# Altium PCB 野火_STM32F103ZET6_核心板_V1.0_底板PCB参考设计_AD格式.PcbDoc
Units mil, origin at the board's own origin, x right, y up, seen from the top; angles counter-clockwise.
Board outline 3896.24 x 5247.31 mil, 2 copper layers (TOP, BOTTOM), stack 10.4 mil thick; 6 components, 115 nets, 124 pads, 0 vias.
Unrouted connection lines stored in the file: 8.
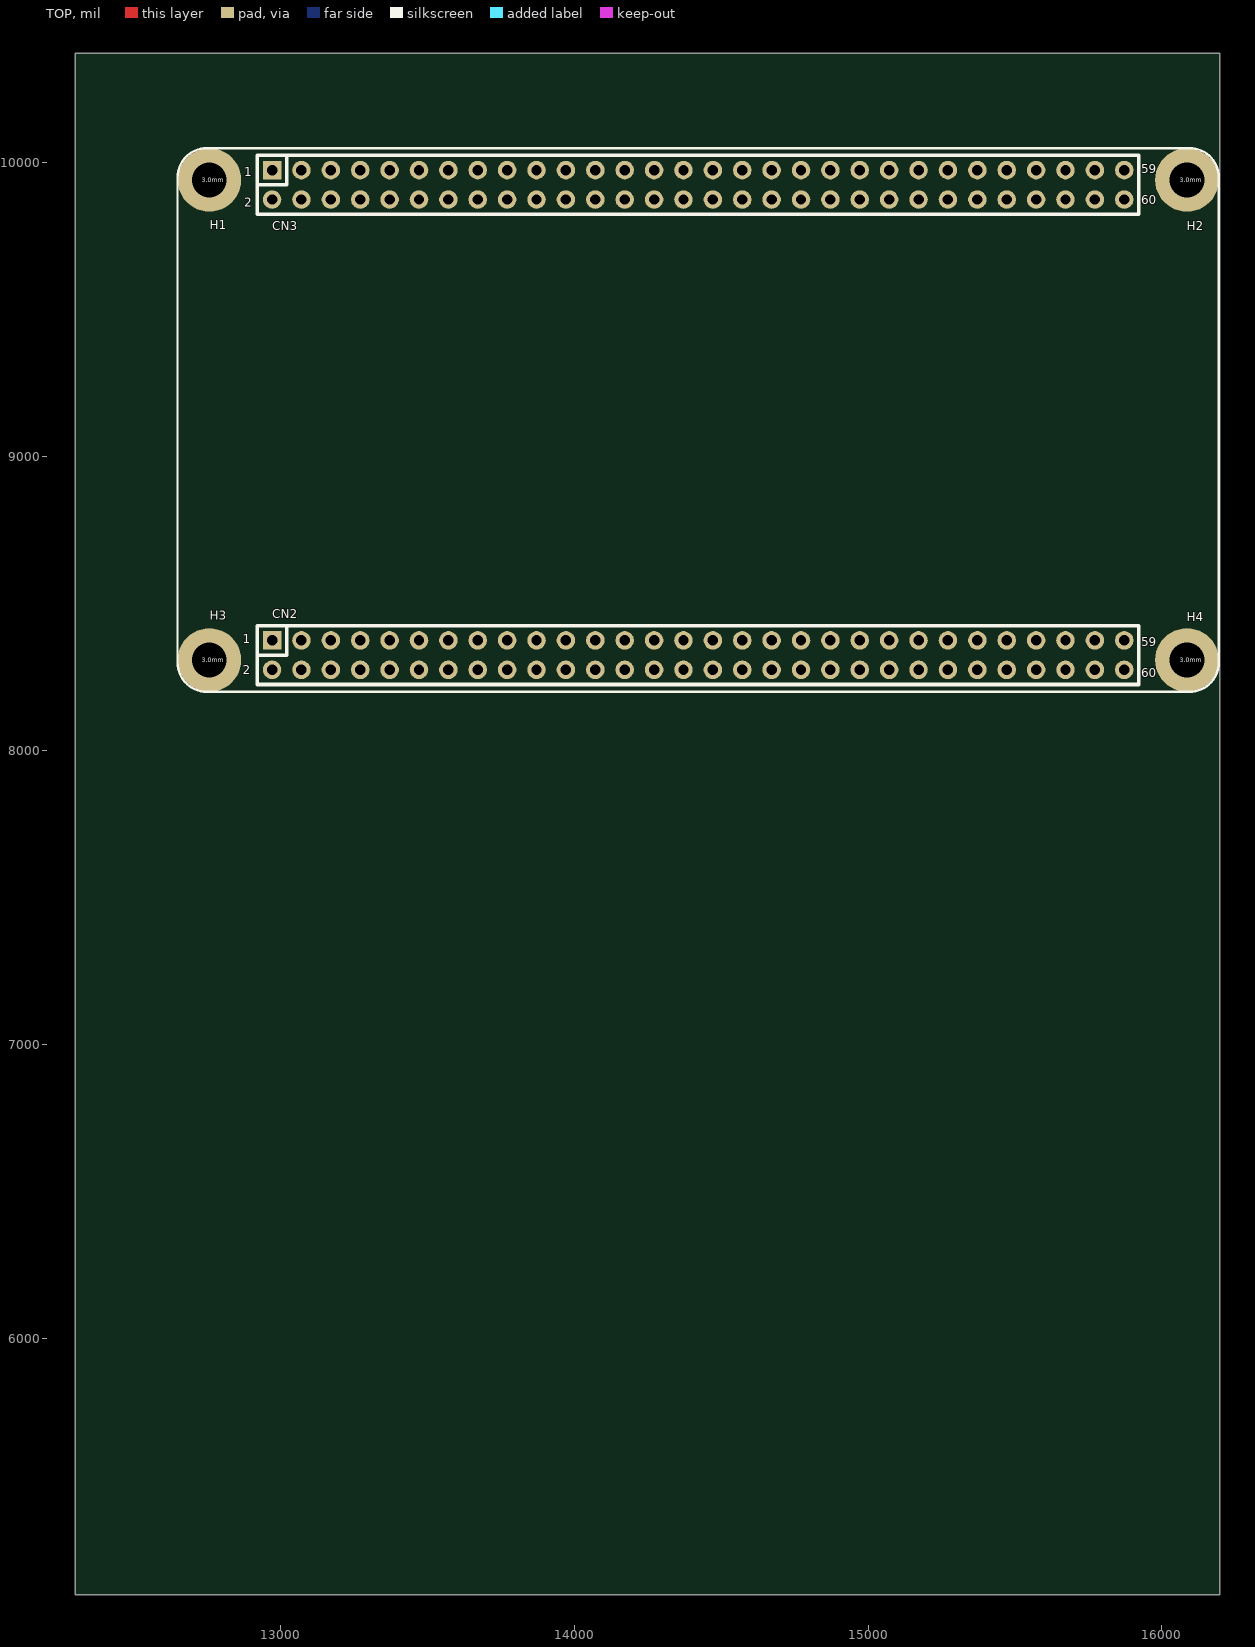
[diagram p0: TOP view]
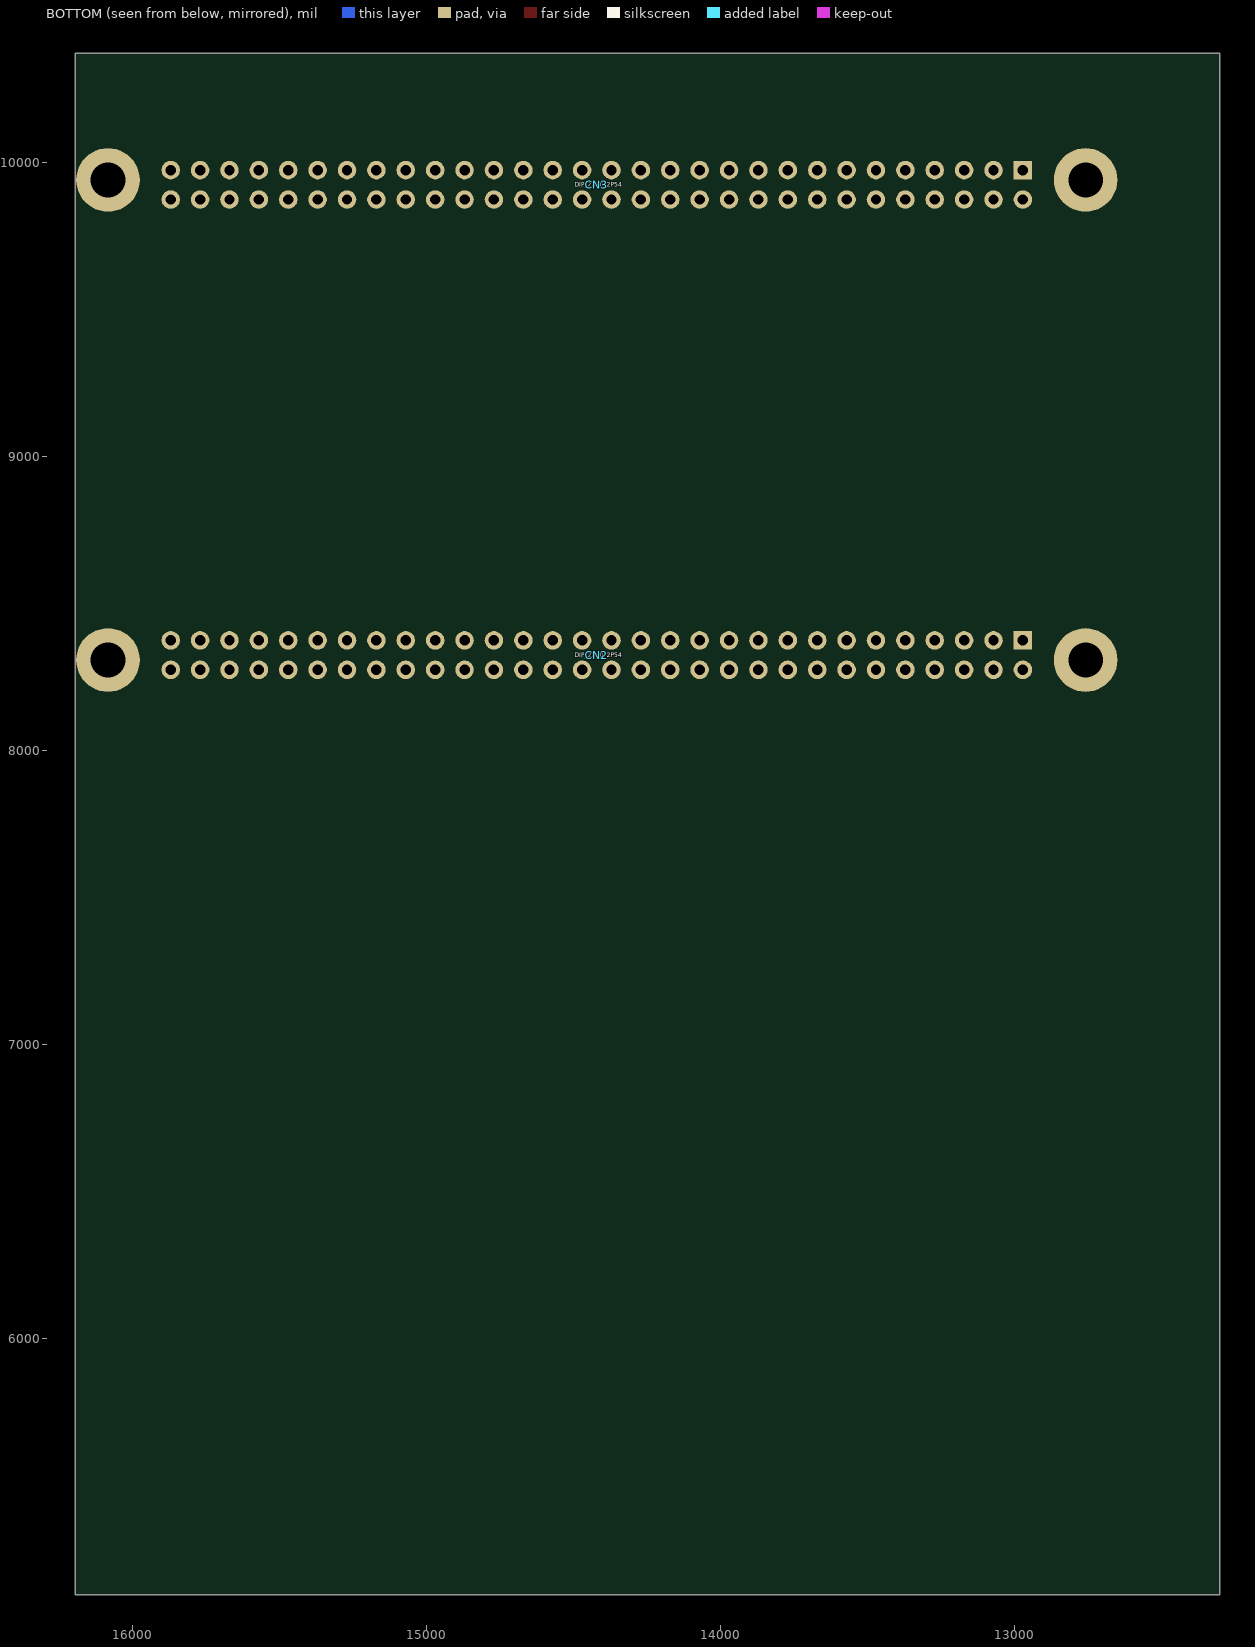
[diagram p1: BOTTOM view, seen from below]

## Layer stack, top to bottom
TOP: signal copper 1.2
Dielectric: core 8, FR-4, Dk 4.5
BOTTOM: signal copper 1.2

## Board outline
12301.07,5126.62 16197.31,5126.62 16197.31,10373.93 12301.07,10373.93

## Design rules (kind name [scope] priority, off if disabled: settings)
Clearance [All] p1: gap=10
PlaneConnect [All] p1: planeconnectstyle=Direct reliefexpansion=20 reliefentries=4 reliefconductorwidth=10 reliefairgap=10
PolygonConnect [All] p1: connectstyle=Direct reliefconductorwidth=10 reliefentries=4 polygonreliefangle="90 Angle" airgapwidth=10
RoutingVias [All] p1: holewidth=28 width=50 viastyle="Through Hole" minholewidth=28 minwidth=50 maxholewidth=28 maxwidth=50
SolderMaskExpansion [All] p1: expansion=4
Width [All] p1: maxlimit=10 minlimit=10 preferedwidth=10 impedancedriven=TRUE minimp=0.000000 maximp=0.000000 favimp=100000000000000005400000000000000.000000
27 further rules are at their usual default settings.

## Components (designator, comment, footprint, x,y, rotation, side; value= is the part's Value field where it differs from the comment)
CN2 "DIP_2X40_0_DIP-2X302P54_DIP_2X3" DIP-2X302P54 14431.15,8325 r180 bottom
CN3 "DIP_2X40_0_DIP-2X302P54_DIP_2X3" DIP-2X302P54 14431.15,9925.39 r180 bottom
H1 "SPACER_0_T3-5P5_IC_3.0MM" T3-5P5 12758.26,9942.13 r0 top
H2 "SPACER_0_T3-5P5_IC_3.0MM" T3-5P5 16085.04,9942.13 r0 top
H3 "SPACER_0_T3-5P5_IC_3.0MM" T3-5P5 12758.26,8308.26 r0 top
H4 "SPACER_0_T3-5P5_IC_3.0MM" T3-5P5 16085.04,8308.26 r0 top

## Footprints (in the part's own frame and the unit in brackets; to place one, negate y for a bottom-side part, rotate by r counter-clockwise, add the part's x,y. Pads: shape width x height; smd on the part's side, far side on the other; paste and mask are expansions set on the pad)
DIP-2X302P54 [mil] "DIP-2X302P54"
  rect 62.99x62.99 / inner round 60 / far side rect 62.99x62.99 hole 35.43: 1(1459.5,50)
  round 62.99 / inner round 60 / far side round 62.99 hole 35.43: 2(1459.5,-50) 3(1359.5,50) 4(1359.5,-50) 5(1259.5,50) 6(1259.5,-50) 7(1159.5,50) 8(1159.5,-50) 9(1059.5,50) 10(1059.5,-50) 11(959.5,50) 12(959.5,-50) 13(859.5,50) 14(859.5,-50) 15(759.5,50) 16(759.5,-50) 17(659.5,50) 18(659.5,-50) 19(559.5,50) 20(559.5,-50) 21(459.5,50) 22(459.5,-50) 23(359.5,50) 24(359.5,-50) 25(259.5,50) 26(259.5,-50) 27(159.5,50) 28(159.5,-50) 29(59.5,50) 30(59.5,-50) 31(-40.5,50) 32(-40.5,-50) 33(-140.5,50) 34(-140.5,-50) 35(-240.5,50) 36(-240.5,-50) 37(-340.5,50) 38(-340.5,-50) 39(-440.5,50) 40(-440.5,-50) 41(-540.5,50) 42(-540.5,-50) 43(-640.5,50) 44(-640.5,-50) 45(-740.5,50) 46(-740.5,-50) 47(-840.5,50) 48(-840.5,-50) 49(-940.5,50) 50(-940.5,-50) 51(-1040.5,50) 52(-1040.5,-50) 53(-1140.5,50) 54(-1140.5,-50) 55(-1240.5,50) 56(-1240.5,-50) 57(-1340.5,50) 58(-1340.5,-50) 59(-1440.5,50) 60(-1440.5,-50)
T3-5P5 [mm] "T3-5P5"
  round 5.5 / inner round 1.524 / far side round 5.5 hole 3: 1(0,0)

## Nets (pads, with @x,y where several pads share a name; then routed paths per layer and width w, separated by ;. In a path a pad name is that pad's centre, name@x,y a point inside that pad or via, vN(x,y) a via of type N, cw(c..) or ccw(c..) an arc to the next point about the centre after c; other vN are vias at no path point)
3V3: CN2.59 CN2.60
BOOT0: CN2.9
GND: CN2.7 CN2.8 CN2.57 CN2.58 CN3.46 H1.1 H2.1 H3.1 H4.1
NRST: CN3.6
PA0/WKUP: CN2.55
PA1: CN3.59
PA2: CN2.12
PA3: CN2.14
PA4: CN2.1
PA5: CN2.2
PA6: CN2.3
PA7: CN2.4
PA8: CN3.19
PA9: CN2.11
PA10: CN2.13
PA11: CN3.37
PA12: CN3.38
PA13: CN3.3
PA14: CN3.2
PA15: CN3.1
PB0: CN2.52
PB1: CN2.53
PB2: CN2.10
PB3: CN3.4
PB4: CN3.5
PB5: CN2.51
PB6: CN2.5
PB7: CN2.6
PB8: CN3.22
PB9: CN3.24
PB10: CN3.26
PB11: CN3.28
PB12: CN3.13
PB13: CN3.8
PB14: CN3.9
PB15: CN3.10
PC0: CN3.29
PC1: CN3.32
PC2: CN3.31
PC3: CN3.15
PC4: CN3.23
PC5: CN3.17
PC6: CN3.27
PC7: CN3.30
PC8: CN3.53
PC9: CN3.55
PC10: CN3.57
PC11: CN3.54
PC12: CN3.58
PC13/TAMPER: CN2.56
PD0: CN2.37
PD1: CN2.38
PD2: CN3.56
PD3: CN3.20
PD4: CN3.41
PD5: CN3.42
PD6: CN3.18
PD7: CN3.52
PD8: CN2.48
PD9: CN2.49
PD10: CN2.50
PD11: CN2.31
PD12: CN2.32
PD13: CN2.33
PD14: CN2.35
PD15: CN2.36
PE0: CN3.43
PE1: CN3.44
PE2: CN3.39
PE3: CN3.14
PE4: CN3.25
PE5: CN3.21
PE6: CN3.16
PE7: CN2.39
PE8: CN2.40
PE9: CN2.41
PE10: CN2.42
PE11: CN2.43
PE12: CN2.44
PE13: CN2.45
PE14: CN2.46
PE15: CN2.47
PF0: CN2.15
PF1: CN2.16
PF2: CN2.17
PF3: CN2.18
PF4: CN2.19
PF5: CN2.20
PF6: CN3.34
PF7: CN3.36
PF8: CN2.54
PF9: CN3.47
PF10: CN3.49
PF11: CN3.50
PF12: CN2.21
PF13: CN2.22
PF14: CN2.23
PF15: CN2.24
PG0: CN2.25
PG1: CN2.26
PG2: CN2.27
PG3: CN2.28
PG4: CN2.29
PG5: CN2.30
PG6: CN3.35
PG7: CN3.33
PG8: CN3.11
PG9: CN3.7
PG10: CN3.40
PG11: CN3.48
PG12: CN2.34
PG13: CN3.45
PG14: CN3.51
PG15: CN3.12
VBAT: CN3.60

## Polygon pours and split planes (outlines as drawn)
no net on Top Solder (solid): 16193.31,8299.99 16193.31,8416.53 16085.04,8416.53 16075.6,8416.12 16066.24,8414.89 16057.02,8412.84 16048.01,8410 16039.28,8406.39 16030.91,8402.02 16022.94,8396.95 16015.45,8391.2 16008.48,8384.82 16002.1,8377.85 15996.35,8370.36 15991.28,8362.4 15986.91,8354.02 15983.3,8345.29 15980.46,8336.28 15978.41,8327.06 15977.18,8317.7 15976.77,8308.26 15976.77,8199.99 16093.31,8199.99 16102.03,8200.37 16110.67,8201.51 16119.19,8203.4 16127.51,8206.02 16135.57,8209.36 16143.31,8213.39 16150.67,8218.07 16157.59,8223.39 16164.02,8229.28 16169.91,8235.71 16175.23,8242.63 16179.91,8249.99 16183.94,8257.73 16187.28,8265.79 16189.9,8274.11 16191.79,8282.63 16192.93,8291.27 16193.31,8299.99
no net on Top Solder (solid): 16193.31,9833.86 16193.31,9950.4 16192.93,9959.12 16191.79,9967.76 16189.9,9976.28 16187.28,9984.6 16183.94,9992.66 16179.91,10000.4 16175.23,10007.76 16169.91,10014.68 16164.02,10021.11 16157.59,10027 16150.67,10032.32 16143.31,10037 16135.57,10041.03 16127.51,10044.37 16119.19,10046.99 16110.67,10048.88 16102.03,10050.02 16093.31,10050.4 15976.77,10050.4 15976.77,9942.13 15977.18,9932.69 15978.41,9923.33 15980.46,9914.11 15983.3,9905.1 15986.91,9896.37 15991.28,9888 15996.35,9880.03 16002.1,9872.54 16008.48,9865.57 16015.45,9859.19 16022.94,9853.44 16030.91,9848.37 16039.28,9844 16048.01,9840.39 16057.02,9837.55 16066.24,9835.5 16075.6,9834.27 16085.04,9833.86 16193.31,9833.86
no net on Top Solder (solid): 12866.53,8199.99 12866.53,8308.26 12866.12,8317.7 12864.89,8327.06 12862.84,8336.28 12860,8345.29 12856.39,8354.02 12852.02,8362.4 12846.95,8370.36 12841.2,8377.85 12834.82,8384.82 12827.85,8391.2 12820.36,8396.95 12812.4,8402.02 12804.02,8406.39 12795.29,8410 12786.28,8412.84 12777.06,8414.89 12767.7,8416.12 12758.26,8416.53 12649.99,8416.53 12649.99,8299.99 12650.37,8291.27 12651.51,8282.63 12653.4,8274.11 12656.02,8265.79 12659.36,8257.73 12663.39,8249.99 12668.07,8242.63 12673.39,8235.71 12679.28,8229.28 12685.71,8223.39 12692.63,8218.07 12699.99,8213.39 12707.73,8209.36 12715.79,8206.02 12724.11,8203.4 12732.63,8201.51 12741.27,8200.37 12749.99,8199.99 12866.53,8199.99
no net on Top Solder (solid): 12866.53,9942.13 12866.53,10050.4 12749.99,10050.4 12741.27,10050.02 12732.63,10048.88 12724.11,10046.99 12715.79,10044.37 12707.73,10041.03 12699.99,10037 12692.63,10032.32 12685.71,10027 12679.28,10021.11 12673.39,10014.68 12668.07,10007.76 12663.39,10000.4 12659.36,9992.66 12656.02,9984.6 12653.4,9976.28 12651.51,9967.76 12650.37,9959.12 12649.99,9950.4 12649.99,9833.86 12758.26,9833.86 12767.7,9834.27 12777.06,9835.5 12786.28,9837.55 12795.29,9840.39 12804.02,9844 12812.4,9848.37 12820.36,9853.44 12827.85,9859.19 12834.82,9865.57 12841.2,9872.54 12846.95,9880.03 12852.02,9888 12856.39,9896.37 12860,9905.1 12862.84,9914.11 12864.89,9923.33 12866.12,9932.69 12866.53,9942.13
no net on Bottom Solder (solid): 16193.31,8299.99 16193.31,8416.53 16085.04,8416.53 16075.6,8416.12 16066.24,8414.89 16057.02,8412.84 16048.01,8410 16039.28,8406.39 16030.91,8402.02 16022.94,8396.95 16015.45,8391.2 16008.48,8384.82 16002.1,8377.85 15996.35,8370.36 15991.28,8362.4 15986.91,8354.02 15983.3,8345.29 15980.46,8336.28 15978.41,8327.06 15977.18,8317.7 15976.77,8308.26 15976.77,8199.99 16093.31,8199.99 16102.03,8200.37 16110.67,8201.51 16119.19,8203.4 16127.51,8206.02 16135.57,8209.36 16143.31,8213.39 16150.67,8218.07 16157.59,8223.39 16164.02,8229.28 16169.91,8235.71 16175.23,8242.63 16179.91,8249.99 16183.94,8257.73 16187.28,8265.79 16189.9,8274.11 16191.79,8282.63 16192.93,8291.27 16193.31,8299.99
no net on Bottom Solder (solid): 16193.31,9833.86 16193.31,9950.4 16192.93,9959.12 16191.79,9967.76 16189.9,9976.28 16187.28,9984.6 16183.94,9992.66 16179.91,10000.4 16175.23,10007.76 16169.91,10014.68 16164.02,10021.11 16157.59,10027 16150.67,10032.32 16143.31,10037 16135.57,10041.03 16127.51,10044.37 16119.19,10046.99 16110.67,10048.88 16102.03,10050.02 16093.31,10050.4 15976.77,10050.4 15976.77,9942.13 15977.18,9932.69 15978.41,9923.33 15980.46,9914.11 15983.3,9905.1 15986.91,9896.37 15991.28,9888 15996.35,9880.03 16002.1,9872.54 16008.48,9865.57 16015.45,9859.19 16022.94,9853.44 16030.91,9848.37 16039.28,9844 16048.01,9840.39 16057.02,9837.55 16066.24,9835.5 16075.6,9834.27 16085.04,9833.86 16193.31,9833.86
no net on Bottom Solder (solid): 12866.53,8199.99 12866.53,8308.26 12866.12,8317.7 12864.89,8327.06 12862.84,8336.28 12860,8345.29 12856.39,8354.02 12852.02,8362.4 12846.95,8370.36 12841.2,8377.85 12834.82,8384.82 12827.85,8391.2 12820.36,8396.95 12812.4,8402.02 12804.02,8406.39 12795.29,8410 12786.28,8412.84 12777.06,8414.89 12767.7,8416.12 12758.26,8416.53 12649.99,8416.53 12649.99,8299.99 12650.37,8291.27 12651.51,8282.63 12653.4,8274.11 12656.02,8265.79 12659.36,8257.73 12663.39,8249.99 12668.07,8242.63 12673.39,8235.71 12679.28,8229.28 12685.71,8223.39 12692.63,8218.07 12699.99,8213.39 12707.73,8209.36 12715.79,8206.02 12724.11,8203.4 12732.63,8201.51 12741.27,8200.37 12749.99,8199.99 12866.53,8199.99
no net on Bottom Solder (solid): 12866.53,9942.13 12866.53,10050.4 12749.99,10050.4 12741.27,10050.02 12732.63,10048.88 12724.11,10046.99 12715.79,10044.37 12707.73,10041.03 12699.99,10037 12692.63,10032.32 12685.71,10027 12679.28,10021.11 12673.39,10014.68 12668.07,10007.76 12663.39,10000.4 12659.36,9992.66 12656.02,9984.6 12653.4,9976.28 12651.51,9967.76 12650.37,9959.12 12649.99,9950.4 12649.99,9833.86 12758.26,9833.86 12767.7,9834.27 12777.06,9835.5 12786.28,9837.55 12795.29,9840.39 12804.02,9844 12812.4,9848.37 12820.36,9853.44 12827.85,9859.19 12834.82,9865.57 12841.2,9872.54 12846.95,9880.03 12852.02,9888 12856.39,9896.37 12860,9905.1 12862.84,9914.11 12864.89,9923.33 12866.12,9932.69 12866.53,9942.13

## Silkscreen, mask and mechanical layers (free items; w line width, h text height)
Top Overlay:
  lines w8: 12650,8300 ccw(c12750,8300) 12750,8200 16093.3,8200 ccw(c16093.3,8300) 16193.3,8300 16193.3,9950.39 ccw(c16093.3,9950.39) 16093.3,10050.39 12750,10050.39 ccw(c12750,9950.39) 12650,9950.39 12650,8300
  text "59" at 15929.5,9965 h30
  text "1" at 12877.5,9955 h30
  text "60" at 15929.5,9860 h30
  text "2" at 12877.5,9850 h30
  text "1" at 12872.5,8365 h30
  text "59" at 15929.5,8355 h30
  text "2" at 12872.5,8260 h30
  text "60" at 15929.5,8250 h30
DRAWING_ORIGIN:
  lines w1: 12625,8200 12675,8200 ; 12650,8175 12650,8225
DIMENSION:
  lines w1: 12375.4,8357.48 12400,8200 ; 12375.4,8357.48 12424.6,8357.48 ; 12375.4,8357.48 12400,8200 ; 12375.4,8357.48 12424.6,8357.48 ; 12375.4,9892.9 12400,10050.38 ; 12375.4,9892.9 12424.6,9892.9 ; 12375.4,9892.9 12400,10050.38 ; 12375.4,9892.9 12424.6,9892.9 ; 12400,8200 12424.6,8357.48 ; 12400,8200 12400,9122 12400,8200 ; 12400,8200 12424.6,8357.48 ; 12400,10050.38 12424.6,9892.9 ; 12400,10050.38 12400,9228 12400,10050.38 ; 12400,10050.38 12424.6,9892.9 ; 12650,10275 12807.48,10299.6 ; 12650,10275 12807.48,10250.4 ; 12650,10275 14256.5,10275 12650,10275 ; 12650,10275 12807.48,10299.6 ; 12650,10275 12807.48,10250.4 ; 12807.48,10250.4 12807.48,10299.6 ; 12807.48,10250.4 12807.48,10299.6 ; 16035.77,10250.4 16193.25,10275 ; 16035.77,10250.4 16035.77,10299.6 ; 16035.77,10250.4 16193.25,10275 ; 16035.77,10250.4 16035.77,10299.6 ; 16035.77,10299.6 16193.25,10275 ; 16035.77,10299.6 16193.25,10275 ; 16193.25,10275 14393.5,10275 16193.25,10275 ; 12301.57,8200 12651.57,8200 12301.57,8200 ; 12301.57,10050.38 12652.97,10050.38 12301.57,10050.38 ; 12650,10048.82 12650,10373.43 12650,10048.82 ; 16193.25,10045.78 16193.25,10373.43 16193.25,10045.78
  text "90" at 14289.5,10255 h40
  text "90" at 14289.5,10255 h40
  text "47" at 12364.5,9155 h40
  text "47" at 12364.5,9155 h40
